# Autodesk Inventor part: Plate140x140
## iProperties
Created: 2006-02
Part Number: Plate140x140
Document SubType Name: Modeling
Designer: 40664
Mass: 196 g
Surface Area: 448 cm^2
Volume: 196 cm^3
Density: 1 g/cm^3
CSToolsMass: 0.2
CSToolsVolume: 196000.0
CSToolsArea: 448.0
Author: 40664
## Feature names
1. Extrusion1
